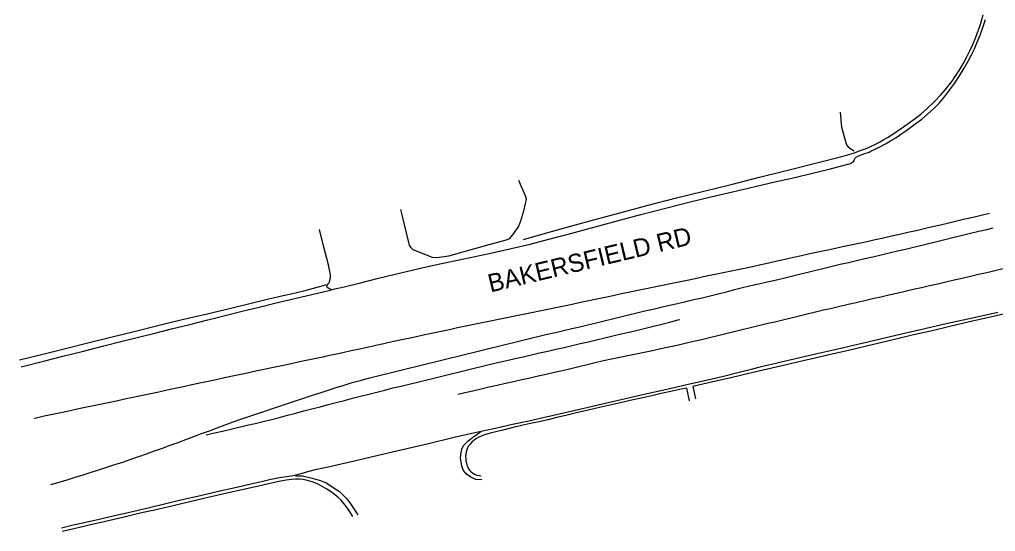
# Model space of a CAD drawing. Extents: x 1970211 to 1973046, y 801032 to 804001.
# Drawn here: x 1972532.6 to 1972824, y 801152.5 to 801305.3 of the extents above; entities that cross this region are included whole.
import ezdxf

# ---------------------------------------------------------------- set-up
doc = ezdxf.new("R2010")
doc.units = 0
for name, color, linetype in [('RD_EX_Conc', 7, 'Continuous'), ('RD_EX_Road', 7, 'Continuous'), ('RD_EX_Road_Paint', 7, 'Continuous'), ('RD_TX_RoadID', 7, 'Continuous')]:
    doc.layers.add(name, color=color, linetype=linetype)

msp = doc.modelspace()

# ---------------------------------------------------------------- linework, layer by layer
at = {"layer": 'RD_EX_Conc'}
for points in [[(1972683.09, 801239.66), (1972689.65, 801241.49), (1972695.71, 801243.19), (1972704.81, 801245.72), (1972712.24, 801247.75), (1972720.37, 801249.9), (1972728.76, 801252.05), (1972736.97, 801254.1), (1972745.08, 801256.11), (1972753.18, 801258.12), (1972761.61, 801260.23), (1972770.72, 801262.52), (1972778.19, 801264.44), (1972781.69, 801265.45), (1972782.95, 801265.91), (1972783.68, 801266.18), (1972784.21, 801266.37), (1972784.87, 801266.62), (1972785.71, 801266.96), (1972786.77, 801267.42), (1972788.02, 801268.01), (1972789.41, 801268.73), (1972790.74, 801269.46), (1972791.84, 801270.07), (1972793.44, 801271.1), (1972796.3, 801273.07), (1972799.41, 801275.29), (1972801.77, 801277.1), (1972803.78, 801278.83), (1972805.87, 801280.83), (1972807.75, 801282.79), (1972809.14, 801284.42), (1972810.2, 801285.78), (1972811.07, 801286.95), (1972811.99, 801288.28), (1972813.16, 801290.08), (1972814.4, 801292.13), (1972815.51, 801294.18), (1972816.48, 801296.13), (1972817.28, 801297.87), (1972817.99, 801299.57), (1972818.7, 801301.41), (1972819.34, 801303.24), (1972819.87, 801304.88), (1972820.39, 801306.73)], [(1972532.57, 801203.71), (1972540.37, 801205.65), (1972546.68, 801207.21), (1972553.01, 801208.77), (1972559.84, 801210.46), (1972566.82, 801212.19), (1972573.92, 801213.96), (1972581.18, 801215.72), (1972588.57, 801217.48), (1972595.68, 801219.18), (1972602.16, 801220.75), (1972606.15, 801221.72), (1972607.88, 801222.13), (1972610.44, 801222.72), (1972614.11, 801223.56), (1972617.47, 801224.37), (1972620.34, 801225.11), (1972622.99, 801225.84), (1972624.25, 801226.21)], [(1972826.86, 801217.47), (1972822.03, 801216.35), (1972816.3, 801215.03), (1972810.4, 801213.65), (1972804.7, 801212.33), (1972799.54, 801211.14), (1972795.17, 801210.12), (1972791.8, 801209.32), (1972788.9, 801208.62), (1972785.9, 801207.91), (1972782.61, 801207.14), (1972778.84, 801206.26), (1972774.77, 801205.32), (1972770.6, 801204.35), (1972766.64, 801203.43), (1972763.2, 801202.62), (1972759.8, 801201.81), (1972755.97, 801200.91), (1972752.04, 801200), (1972748.33, 801199.15), (1972744.58, 801198.29), (1972740.51, 801197.37), (1972736.67, 801196.5), (1972733.62, 801195.8), (1972734.44, 801192.04)], [(1972732.65, 801191.45), (1972731.88, 801195.27), (1972729.69, 801194.86), (1972727.05, 801194.3), (1972724.21, 801193.66), (1972721.45, 801193.02), (1972718.69, 801192.39), (1972715.87, 801191.74), (1972712.82, 801191.05), (1972709.34, 801190.27), (1972705.77, 801189.47), (1972702.45, 801188.72), (1972699.27, 801187.99), (1972696.09, 801187.23), (1972693.06, 801186.5), (1972690.31, 801185.85), (1972687.73, 801185.26), (1972685.19, 801184.68), (1972682.53, 801184.08), (1972679.6, 801183.4), (1972676.87, 801182.76), (1972674.84, 801182.27), (1972673.15, 801181.83), (1972671.44, 801181.29), (1972669.98, 801180.75), (1972669.02, 801180.26), (1972668.33, 801179.76), (1972667.67, 801179.17), (1972667.11, 801178.56), (1972666.69, 801178.01), (1972666.38, 801177.46), (1972666.14, 801176.87), (1972665.97, 801176.24), (1972665.86, 801175.56), (1972665.81, 801174.87), (1972665.82, 801174.21), (1972665.88, 801173.56), (1972666.02, 801172.93), (1972666.21, 801172.31), (1972666.42, 801171.73), (1972666.69, 801171.19), (1972667.04, 801170.71), (1972667.47, 801170.28), (1972667.97, 801169.93), (1972668.45, 801169.64), (1972668.83, 801169.42), (1972669.05, 801169.33), (1972669.85, 801169.17), (1972670.43, 801169.1)], [(1972670.64, 801167.9), (1972668.85, 801168.02), (1972667.39, 801168.66), (1972666.05, 801169.55), (1972665.14, 801170.66), (1972664.63, 801172), (1972664.34, 801173.84), (1972664.31, 801174.24), (1972664.38, 801175.49), (1972664.7, 801177.02), (1972665.15, 801178.12), (1972666.53, 801179.54), (1972667.82, 801180.54), (1972669.28, 801181.49), (1972670.29, 801182.2)], [(1972614.95, 801169.11), (1972617.07, 801169.05), (1972619.61, 801168.47), (1972621.8, 801167.86), (1972624.09, 801167.06), (1972626.22, 801165.64), (1972628.09, 801164.43), (1972630.11, 801162.42), (1972631.28, 801160.91), (1972632.41, 801159.24), (1972633.59, 801157.42)]]:
    msp.add_lwpolyline(points, dxfattribs=at)
at = {"layer": 'RD_EX_Road'}
for points in [[(1972533.08, 801201.66), (1972540.09, 801203.42), (1972545.54, 801204.79), (1972551.29, 801206.25), (1972557.74, 801207.89), (1972563.22, 801209.28), (1972567.7, 801210.39), (1972572.58, 801211.61), (1972578.01, 801212.96), (1972583.44, 801214.31), (1972588.78, 801215.62), (1972593.98, 801216.92), (1972599.06, 801218.21), (1972604.11, 801219.46), (1972609.26, 801220.7), (1972615.19, 801222.11), (1972621.52, 801223.62), (1972625.33, 801224.53), (1972626.76, 801224.88), (1972629.49, 801225.55), (1972634.03, 801226.66), (1972639.81, 801228.06), (1972646.49, 801229.68), (1972652.77, 801231.16), (1972658.62, 801232.48), (1972665.31, 801233.92), (1972672.79, 801235.49), (1972679.4, 801236.95), (1972685.04, 801238.29), (1972690.63, 801239.72), (1972696.43, 801241.28), (1972703.02, 801243.06), (1972710.41, 801245.05), (1972718.12, 801247.09), (1972725.9, 801249.1), (1972732.87, 801250.87), (1972739.03, 801252.39), (1972745.49, 801253.92), (1972752.24, 801255.48), (1972758.13, 801256.82), (1972763.18, 801257.98), (1972768.63, 801259.27), (1972774.38, 801260.67), (1972778.48, 801261.71), (1972780.71, 801262.38), (1972781.37, 801262.71), (1972781.76, 801263.06), (1972782.02, 801263.81), (1972782.43, 801264.2), (1972783.11, 801264.59), (1972785.04, 801265.32), (1972786.3, 801265.77), (1972786.84, 801265.98), (1972787.88, 801266.47), (1972789.53, 801267.29), (1972791.17, 801268.17), (1972792.72, 801269.08), (1972794.26, 801270.04), (1972795.8, 801271.05), (1972797.32, 801272.1), (1972798.81, 801273.18), (1972800.38, 801274.34), (1972802.03, 801275.62), (1972803.79, 801277.08), (1972805.64, 801278.72), (1972807.32, 801280.46), (1972808.82, 801282.28), (1972810.32, 801284.21), (1972811.83, 801286.26), (1972813.31, 801288.46), (1972814.72, 801290.76), (1972815.91, 801292.86), (1972816.88, 801294.74), (1972817.77, 801296.61), (1972818.6, 801298.51), (1972819.43, 801300.61), (1972820.26, 801302.91), (1972821.06, 801305.35)], [(1972777.7, 801277.67), (1972778.02, 801273.16), (1972779.56, 801267.92), (1972780.06, 801267.36), (1972780.83, 801266.67), (1972781.83, 801266.16)], [(1972646.37, 801248.61), (1972646.73, 801247.05), (1972648.05, 801241.59), (1972648.91, 801237.98), (1972649.3, 801237.35), (1972650.01, 801236.7), (1972655.83, 801234.35), (1972657.21, 801234.28), (1972660.82, 801234.78), (1972665.37, 801236.08), (1972672.79, 801238.16), (1972677.63, 801239.42), (1972678.98, 801239.99), (1972680.25, 801241.43), (1972681.7, 801243.59), (1972682.25, 801245.2), (1972683.17, 801248.24), (1972683.8, 801250.82), (1972683.94, 801251.56), (1972683.68, 801252.72), (1972682.53, 801255.37), (1972681.66, 801257.24)], [(1972625.61, 801224.7), (1972624.92, 801225.07), (1972624.49, 801225.3), (1972624.39, 801225.52), (1972624.34, 801225.7), (1972624.42, 801225.96), (1972624.78, 801226.5), (1972625.02, 801226.68), (1972625.15, 801227.07), (1972625.41, 801228.19), (1972625.48, 801229.11), (1972624.82, 801232.11), (1972623.43, 801237.33), (1972622.12, 801242.67)], [(1972545.07, 801153.59), (1972548.21, 801154.33), (1972552.34, 801155.27), (1972556.39, 801156.19), (1972560.51, 801157.12), (1972565.39, 801158.25), (1972570.97, 801159.56), (1972576.24, 801160.82), (1972581.17, 801162.01), (1972586.59, 801163.27), (1972592.43, 801164.6), (1972597.5, 801165.75), (1972601.61, 801166.69), (1972604.83, 801167.43), (1972607.24, 801167.96), (1972609.21, 801168.37), (1972610.84, 801168.68), (1972612.32, 801168.91), (1972613.69, 801169.12), (1972615.1, 801169.42), (1972616.65, 801169.84), (1972618.72, 801170.38), (1972621.39, 801171.04), (1972624.72, 801171.8), (1972628.66, 801172.66), (1972632.98, 801173.66), (1972637.63, 801174.79), (1972642.68, 801175.98), (1972648.22, 801177.24), (1972654.71, 801178.76), (1972661.97, 801180.5), (1972668.51, 801182), (1972674.2, 801183.25), (1972679.81, 801184.48), (1972685.18, 801185.66), (1972688.47, 801186.4), (1972689.86, 801186.73), (1972692.08, 801187.24), (1972695.49, 801188.03), (1972699.39, 801188.93), (1972703.67, 801189.92), (1972708.42, 801191.02), (1972713.58, 801192.22), (1972718.68, 801193.36), (1972723.56, 801194.43), (1972727.73, 801195.37), (1972731.41, 801196.23), (1972736.32, 801197.38), (1972742.4, 801198.8), (1972747.49, 801200.02), (1972751.2, 801200.96), (1972753.35, 801201.51), (1972754.58, 801201.83), (1972758.81, 801202.82), (1972766.03, 801204.49), (1972772.07, 801205.89), (1972776.61, 801206.92), (1972781.68, 801208.08), (1972787.61, 801209.47), (1972794.29, 801211.04), (1972801.64, 801212.77), (1972809.31, 801214.53), (1972817.17, 801216.28), (1972824.76, 801218)], [(1972632.15, 801156.98), (1972630.49, 801159.43), (1972629.43, 801160.86), (1972628.6, 801161.81), (1972627.61, 801162.77), (1972626.54, 801163.66), (1972625.49, 801164.43), (1972624.35, 801165.15), (1972623, 801165.93), (1972621.52, 801166.67), (1972619.99, 801167.29), (1972618.54, 801167.75), (1972617.28, 801168.01), (1972616.14, 801168.13), (1972615.03, 801168.15), (1972613.76, 801168.05), (1972612.16, 801167.8), (1972609.55, 801167.26), (1972605.25, 801166.3), (1972599.98, 801165.11), (1972594.44, 801163.88), (1972588.96, 801162.64), (1972583.85, 801161.42), (1972578.87, 801160.23), (1972573.78, 801159.07), (1972568.61, 801157.91), (1972563.41, 801156.7), (1972558.28, 801155.5), (1972553.34, 801154.35), (1972548.44, 801153.21), (1972545.33, 801152.49)]]:
    msp.add_lwpolyline(points, dxfattribs=at)
at = {"layer": 'RD_EX_Road_Paint'}
for points in [[(1972822.25, 801247.39), (1972819.81, 801246.82), (1972817.38, 801246.25), (1972814.94, 801245.68), (1972812.51, 801245.11), (1972810.08, 801244.54), (1972807.64, 801243.97), (1972805.21, 801243.4), (1972802.77, 801242.83), (1972800.34, 801242.28), (1972797.9, 801241.74), (1972795.46, 801241.19), (1972793.02, 801240.64), (1972790.58, 801240.09), (1972788.14, 801239.55), (1972785.7, 801239), (1972783.26, 801238.47), (1972780.81, 801237.95), (1972778.37, 801237.43), (1972775.92, 801236.91), (1972773.48, 801236.38), (1972771.03, 801235.86), (1972768.59, 801235.34), (1972766.15, 801234.8), (1972763.71, 801234.26), (1972761.27, 801233.71), (1972758.83, 801233.16), (1972756.39, 801232.62), (1972753.95, 801232.07), (1972751.51, 801231.52), (1972749.07, 801230.99), (1972746.62, 801230.49), (1972744.17, 801229.98), (1972741.72, 801229.47), (1972739.28, 801228.97), (1972736.83, 801228.46), (1972734.38, 801227.95), (1972731.93, 801227.45), (1972729.48, 801226.94), (1972727.04, 801226.43), (1972724.59, 801225.93), (1972722.14, 801225.42), (1972719.69, 801224.91), (1972717.24, 801224.4), (1972714.8, 801223.9), (1972712.35, 801223.39), (1972709.9, 801222.88), (1972707.46, 801222.37), (1972705.01, 801221.85), (1972702.56, 801221.33), (1972700.12, 801220.81), (1972697.67, 801220.29), (1972695.23, 801219.77), (1972692.78, 801219.25), (1972690.34, 801218.73), (1972687.89, 801218.21), (1972685.44, 801217.72), (1972682.99, 801217.23), (1972680.54, 801216.74), (1972678.09, 801216.25), (1972675.64, 801215.75), (1972673.19, 801215.26), (1972670.73, 801214.77), (1972668.28, 801214.28), (1972665.84, 801213.76), (1972663.39, 801213.24), (1972660.95, 801212.72), (1972658.5, 801212.19), (1972656.06, 801211.67), (1972653.62, 801211.14), (1972651.17, 801210.62), (1972648.73, 801210.09), (1972646.28, 801209.57), (1972643.84, 801209.05), (1972641.4, 801208.52), (1972638.95, 801207.99), (1972636.51, 801207.45), (1972634.07, 801206.92), (1972631.62, 801206.39), (1972629.18, 801205.86), (1972626.74, 801205.33), (1972624.3, 801204.8), (1972623.11, 801204.54)], [(1972541.96, 801166.53), (1972544.37, 801167.21), (1972546.76, 801167.93), (1972549.15, 801168.67), (1972551.54, 801169.41), (1972553.92, 801170.15), (1972556.3, 801170.92), (1972558.68, 801171.69), (1972561.06, 801172.46), (1972563.44, 801173.22), (1972565.8, 801174.05), (1972568.16, 801174.87), (1972570.52, 801175.7), (1972572.88, 801176.52), (1972575.24, 801177.35), (1972577.58, 801178.22), (1972579.92, 801179.09), (1972582.27, 801179.97), (1972584.61, 801180.84), (1972586.95, 801181.71), (1972589.29, 801182.58), (1972591.64, 801183.45), (1972593.99, 801184.31), (1972596.33, 801185.17), (1972598.68, 801186.03), (1972601.05, 801186.82), (1972603.43, 801187.61), (1972605.8, 801188.4), (1972608.17, 801189.19), (1972610.54, 801189.97), (1972612.91, 801190.76), (1972615.29, 801191.55), (1972617.66, 801192.34), (1972620.03, 801193.13), (1972622.4, 801193.92), (1972624.77, 801194.71), (1972627.16, 801195.45), (1972629.55, 801196.19), (1972631.94, 801196.92), (1972634.34, 801197.6), (1972636.77, 801198.22), (1972639.19, 801198.83), (1972641.62, 801199.44), (1972644.04, 801200.04), (1972646.47, 801200.65), (1972648.89, 801201.25), (1972651.32, 801201.86), (1972653.74, 801202.46), (1972656.17, 801203.05), (1972658.6, 801203.64), (1972661.03, 801204.22), (1972663.46, 801204.81), (1972665.89, 801205.39), (1972668.32, 801205.98), (1972670.75, 801206.58), (1972673.18, 801207.19), (1972675.6, 801207.79), (1972678.03, 801208.39), (1972680.45, 801209), (1972682.88, 801209.6), (1972685.31, 801210.21), (1972687.74, 801210.79), (1972690.17, 801211.36), (1972692.61, 801211.92), (1972695.04, 801212.48), (1972697.48, 801213.05), (1972699.91, 801213.61), (1972702.35, 801214.18), (1972704.78, 801214.74), (1972707.21, 801215.34), (1972709.64, 801215.94), (1972712.07, 801216.54), (1972714.49, 801217.13), (1972716.92, 801217.73), (1972719.35, 801218.33), (1972721.78, 801218.89), (1972724.22, 801219.45), (1972726.66, 801220.01), (1972729.09, 801220.57), (1972731.53, 801221.13), (1972733.96, 801221.7), (1972736.4, 801222.27), (1972738.83, 801222.84), (1972741.25, 801223.45), (1972743.68, 801224.07), (1972746.1, 801224.68), (1972748.52, 801225.3), (1972750.95, 801225.9), (1972753.39, 801226.44), (1972755.83, 801226.99), (1972758.27, 801227.53), (1972760.7, 801228.12), (1972763.13, 801228.71), (1972765.56, 801229.3), (1972767.99, 801229.89), (1972770.42, 801230.48), (1972772.84, 801231.07), (1972775.27, 801231.67), (1972777.7, 801232.25), (1972780.14, 801232.82), (1972782.57, 801233.38), (1972785.01, 801233.95), (1972787.44, 801234.52), (1972789.88, 801235.08), (1972792.31, 801235.65), (1972794.75, 801236.22), (1972797.17, 801236.81), (1972799.6, 801237.4), (1972802.03, 801237.99), (1972804.46, 801238.58), (1972806.89, 801239.17), (1972809.32, 801239.76), (1972811.75, 801240.35), (1972814.18, 801240.93), (1972816.61, 801241.51), (1972819.04, 801242.09), (1972821.48, 801242.67), (1972823.35, 801243.12)], [(1972826.3, 801230.87), (1972823.86, 801230.31), (1972821.43, 801229.74), (1972818.99, 801229.17), (1972816.56, 801228.61), (1972814.12, 801228.04), (1972811.69, 801227.48), (1972809.25, 801226.92), (1972806.82, 801226.36), (1972804.38, 801225.8), (1972801.94, 801225.24), (1972799.51, 801224.68), (1972797.07, 801224.12), (1972794.63, 801223.56), (1972792.2, 801223), (1972789.76, 801222.45), (1972787.32, 801221.89), (1972784.89, 801221.33), (1972782.45, 801220.77), (1972780.02, 801220.21), (1972777.58, 801219.65), (1972775.14, 801219.09), (1972772.71, 801218.53), (1972770.28, 801217.94), (1972767.85, 801217.35), (1972765.42, 801216.77), (1972762.99, 801216.18), (1972760.56, 801215.6), (1972758.13, 801215.01), (1972755.7, 801214.43), (1972753.27, 801213.84), (1972750.84, 801213.25), (1972748.4, 801212.67), (1972745.97, 801212.08), (1972743.54, 801211.5), (1972741.11, 801210.91), (1972738.68, 801210.33), (1972736.25, 801209.74), (1972733.82, 801209.16), (1972731.39, 801208.57), (1972728.96, 801208), (1972726.51, 801207.48), (1972724.07, 801206.97), (1972721.62, 801206.46), (1972719.17, 801205.94), (1972716.73, 801205.43), (1972714.28, 801204.92), (1972711.83, 801204.4), (1972709.39, 801203.89), (1972706.94, 801203.38), (1972704.5, 801202.82), (1972702.07, 801202.24), (1972699.64, 801201.65), (1972697.21, 801201.06), (1972694.78, 801200.49), (1972692.34, 801199.94), (1972689.9, 801199.38), (1972687.46, 801198.83), (1972685.03, 801198.28), (1972682.59, 801197.73), (1972680.15, 801197.18), (1972677.71, 801196.62), (1972675.27, 801196.07), (1972672.84, 801195.52), (1972670.4, 801194.97), (1972667.96, 801194.42), (1972665.52, 801193.87), (1972663.52, 801193.41)], [(1972588.35, 801181.33), (1972590.78, 801181.9), (1972593.22, 801182.47), (1972595.65, 801183.05), (1972598.08, 801183.62), (1972600.52, 801184.19), (1972602.95, 801184.76), (1972605.38, 801185.34), (1972607.82, 801185.91), (1972610.24, 801186.53), (1972612.65, 801187.18), (1972615.07, 801187.82), (1972617.49, 801188.46), (1972619.9, 801189.1), (1972622.32, 801189.74), (1972624.73, 801190.39), (1972627.15, 801191.01), (1972629.58, 801191.62), (1972632, 801192.24), (1972634.42, 801192.85), (1972636.85, 801193.47), (1972639.27, 801194.09), (1972641.69, 801194.7), (1972644.11, 801195.32), (1972646.55, 801195.9), (1972648.98, 801196.47), (1972651.41, 801197.05), (1972653.84, 801197.63), (1972656.27, 801198.23), (1972658.69, 801198.84), (1972661.12, 801199.45), (1972663.54, 801200.05), (1972665.97, 801200.65), (1972668.4, 801201.24), (1972670.83, 801201.83), (1972673.26, 801202.43), (1972675.69, 801203.01), (1972678.13, 801203.56), (1972680.57, 801204.11), (1972683, 801204.66), (1972685.44, 801205.22), (1972687.88, 801205.77), (1972690.32, 801206.32), (1972692.76, 801206.87), (1972695.2, 801207.42), (1972697.63, 801207.99), (1972700.06, 801208.57), (1972702.49, 801209.14), (1972704.93, 801209.72), (1972707.36, 801210.3), (1972709.79, 801210.87), (1972712.22, 801211.45), (1972714.66, 801212.02), (1972717.09, 801212.6), (1972719.52, 801213.19), (1972721.95, 801213.77), (1972724.37, 801214.4), (1972726.79, 801215.02), (1972729.21, 801215.65), (1972729.77, 801215.8)], [(1972623.11, 801204.54), (1972620.67, 801204.03), (1972618.22, 801203.51), (1972615.77, 801202.99), (1972613.33, 801202.48), (1972610.88, 801201.96), (1972608.44, 801201.44), (1972605.99, 801200.93), (1972603.55, 801200.41), (1972601.1, 801199.89), (1972598.65, 801199.37), (1972596.21, 801198.86), (1972593.76, 801198.33), (1972591.32, 801197.8), (1972588.88, 801197.28), (1972586.43, 801196.75), (1972583.99, 801196.22), (1972581.54, 801195.7), (1972579.1, 801195.17), (1972576.66, 801194.65), (1972574.21, 801194.12), (1972571.77, 801193.6), (1972569.32, 801193.08), (1972566.88, 801192.56), (1972564.43, 801192.05), (1972561.98, 801191.53), (1972559.54, 801191.01), (1972557.09, 801190.5), (1972554.65, 801189.98), (1972552.2, 801189.46), (1972549.76, 801188.95), (1972547.31, 801188.43), (1972544.87, 801187.9), (1972542.42, 801187.38), (1972539.98, 801186.86), (1972537.53, 801186.33), (1972536.98, 801186.22)]]:
    msp.add_lwpolyline(points, dxfattribs=at)

# ---------------------------------------------------------------- texts
at = {"layer": 'RD_TX_RoadID'}
msp.add_text('BAKERSFIELD RD', height=5.4, rotation=13.4572, dxfattribs=at).set_placement((1972673.2, 801223.81))

doc.saveas('drawing.dxf')
